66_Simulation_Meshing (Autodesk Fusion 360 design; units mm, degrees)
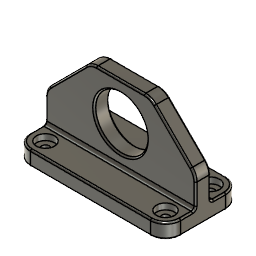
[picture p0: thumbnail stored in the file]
part number: 2026-07-20-13-25-26-316
sketch "Sketch1" plane through (0, 0, 0) normal (0, 1, 0) x axis (1, 0, 0)
  line L1 (-50, 25) -> (50, 25)
  line L2 (-50, -25) -> (-50, 25)
  line L3 (50, -25) -> (-50, -25)
  line L4 (50, 25) -> (50, -25)
  line L5 (-50, -25) -> (50, 25)
  line L6 (50, -25) -> (-50, 25)
  point P6 (0, 0)
  point P1 (0, 0)
  point P4 (-50, -25)
  point P5 (50, -25)
  point P3 (-50, 25)
  horizontal L1
  perpendicular L1 L2
  parallel L1 L3
  parallel L2 L4
  coincident L5 P6
  coincident L6 P6
  coincident P1 P6
  dimension "d2" distance P4 P5 = 100
  dimension "d3" distance P3 P4 = 50
extrude "Extrude1" new body sketch "Sketch1" profile of L1 L2 L3 L4 distance 10
sketch "Sketch2" plane through (0, 0, -25) normal (0, 0, -1) x axis (1, 0, 0)
  line L1 (-50, -5) -> (-50, 5)
  line L2 (50, -5) -> (-50, -5)
  line L3 (50, 5) -> (50, -5)
  line L4 (-50, 5) -> (50, 5)
  line L5 (-50, -25) -> (50, -25)
  line L6 (-50, 25) -> (-50, -25)
  line L7 (50, 25) -> (-50, 25)
  line L8 (50, -25) -> (50, 25)
  line L9 (-50, 25) -> (50, -25)
  line L10 (50, 25) -> (-50, -25)
  point P10 (0, 0)
  point P1 (0, 0)
  point P5 (50, 5)
  point P7 (-50, -25)
  point P8 (-50, 25)
  horizontal L5
  perpendicular L5 L6
  parallel L5 L7
  parallel L6 L8
  coincident L9 P10
  coincident L10 P10
  coincident P1 P10
  coincident P5 L8
  dimension "d6" distance P7 P8 = 50
extrude "Extrude2" add sketch "Sketch2" profile of L1 L2 L3 L4 L5 L6 L7 L8 along normal blind 10
chamfer "Chamfer1" sketch "Sketch2" distance 30
sketch "Sketch3" plane through (0, -5, 0) normal (0, -1, 0) x axis (1, 0, 0)
  line L1 (20, 25) -> (50, -5)
  line L2 (-20, 25) -> (20, 25)
  line L3 (-50, -5) -> (-20, 25)
  line L4 (-50, -25) -> (-50, -5)
  line L5 (50, -25) -> (-50, -25)
  line L6 (50, -5) -> (50, -25)
  circle C1 centre (0, 0) radius 17.5
  point P1 (0, 0)
  point P8 (0, 0)
  coincident P1 P8
  dimension "d10" diameter C1 = 35
extrude "Extrude3" cut sketch "Sketch3" profile of C1 no distance stored
fillet "Fillet1" radius 10
fillet "Fillet2" radius 10
sketch "Sketch4" plane through (0, 0, -25) normal (0, 0, 1) x axis (-1, 0, 0)
  line L1 (50, -5) -> (50, -15)
  line L2 (-50, -5) -> (50, -5)
  line L3 (-50, -15) -> (-50, -5)
  line L4 (40, -25) -> (-40, -25)
  line L5 (-40, 25) -> (40, 25)
  line L6 (-50, 5) -> (-50, 15)
  line L7 (50, 5) -> (-50, 5)
  line L8 (50, 15) -> (50, 5)
  arc A1 centre (40, -15) radius 10 clockwise from (50, -15) to (40, -25)
  arc A2 centre (-40, -15) radius 10 clockwise from (-40, -25) to (-50, -15)
  arc A3 centre (40, 15) radius 10 clockwise from (40, 25) to (50, 15)
  arc A4 centre (-40, 15) radius 10 clockwise from (-50, 15) to (-40, 25)
  point P9 (-40, -15)
  point P18 (-40, -15)
  point P4 (40, -15)
  point P19 (40, -15)
  point P12 (40, 15)
  point P20 (40, 15)
  point P15 (-40, 15)
  point P21 (-40, 15)
  coincident P9 P18
  coincident P4 P19
  coincident P12 P20
  coincident P15 P21
hole "Hole1" sketch "Sketch2" HoleDiameter 5 TipAngle 118 CBDepth 4 CBDiameter 12
fillet "Fillet3" radius 2
fillet "Fillet4" radius 1
chamfer "Chamfer2" sketch "Sketch2" distance 1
